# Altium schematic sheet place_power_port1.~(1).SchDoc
size A4
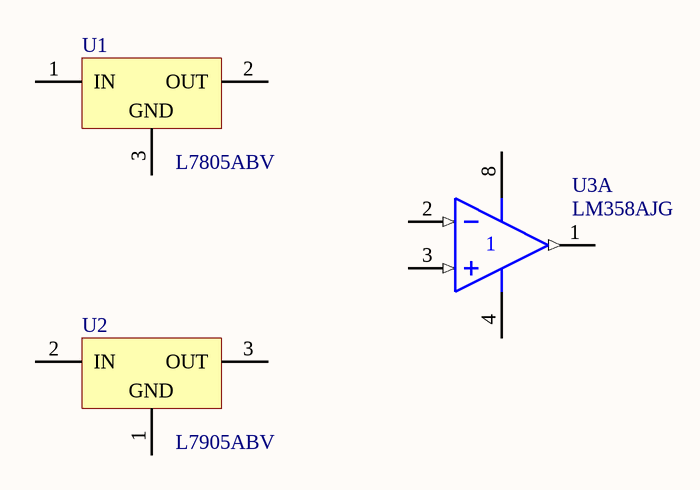
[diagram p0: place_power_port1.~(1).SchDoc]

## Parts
U1  L7805ABV  [TO220ABN]
U2  L7905ABV  [TO220V]
U3  LM358AJG  [JG008]  (part A of 2)

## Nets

Not connected (* = marked no-connect by the designer): U1 1(IN) 2(OUT) 3(GND); U2 1(GND) 2(IN) 3(OUT); U3 1(OUT) 2(IN-) 3(IN+) 4(V-) 8(V+)

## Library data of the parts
U1 = L7805ABV: Precision 1A Regulator; Note: Tab is connected to pin 3 (GND).
U2 = L7905ABV: ?2%Negative Voltage Regulator; Note: Tab is connected to pin 3 (IN).
U3 = LM358AJG: Dual Operational Amplifier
